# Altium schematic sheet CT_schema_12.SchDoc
size 281 x 153 mm
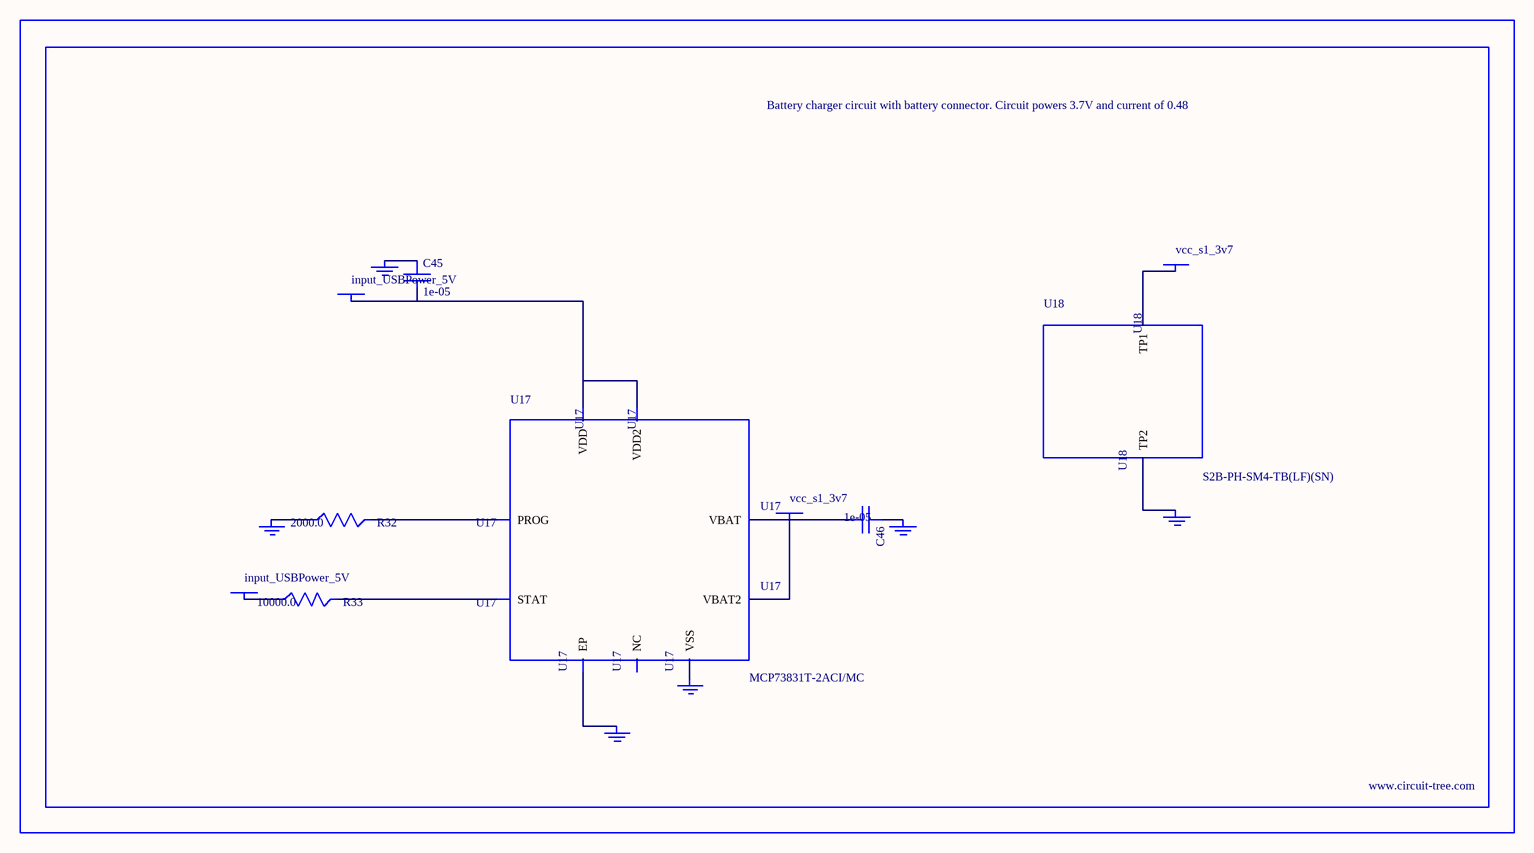
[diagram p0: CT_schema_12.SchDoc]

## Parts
BORDER11  (no value)
C45  1e-05  [C1206]
C46  1e-05  [C1206]
GND_INSTANCE_11_0  (no value)
GND_INSTANCE_11_1  (no value)
GND_INSTANCE_11_2  (no value)
GND_INSTANCE_11_3  (no value)
GND_INSTANCE_11_4  (no value)
GND_INSTANCE_11_5  (no value)
POWER_INSTANCE_11_0  input_USBPower_5V
POWER_INSTANCE_11_1  input_USBPower_5V
POWER_INSTANCE_11_2  vcc_s1_3v7
POWER_INSTANCE_11_3  vcc_s1_3v7
R32  2000.0  [R0603]
R33  10000.0  [R0603]
U17  MCP73831T-2ACI/MC  [DFN8_2X3MC]
U18  S2B-PH-SM4-TB(LF)(SN)  [JST-2-SMD]

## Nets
NetC45_1: C45.1 GND_INSTANCE_11_0.0(GND)
NetC45_2: C45.2 POWER_INSTANCE_11_0.0(PWR) U17.1(VDD) U17.2(VDD2)
NetC46_1: C46.1 GND_INSTANCE_11_1.0(GND)
NetC46_2: C46.2 POWER_INSTANCE_11_2.0(PWR) U17.3(VBAT) U17.4(VBAT2)
NetGND_INSTANCE_11_2_0: GND_INSTANCE_11_2.0(GND) R32.1
NetGND_INSTANCE_11_3_0: GND_INSTANCE_11_3.0(GND) U17.9(EP)
NetGND_INSTANCE_11_4_0: GND_INSTANCE_11_4.0(GND) U17.6(VSS)
NetGND_INSTANCE_11_5_0: GND_INSTANCE_11_5.0(GND) U18.2(TP2)
NetPOWER_INSTANCE_11_1_0: POWER_INSTANCE_11_1.0(PWR) R33.1
NetPOWER_INSTANCE_11_3_0: POWER_INSTANCE_11_3.0(PWR) U18.1(TP1)
NetR32_2: R32.2 U17.8(PROG)
NetR33_2: R33.2 U17.5(STAT)

Not connected (* = marked no-connect by the designer): U17 7(NC)

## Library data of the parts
BORDER11 = BORDER_PAGE11
C45 C46 = C1206C106K3RACTU
GND_INSTANCE_11_0-GND_INSTANCE_11_5 = GND
POWER_INSTANCE_11_0-POWER_INSTANCE_11_3 = PWR
R32 = RC0603JR-072KL
R33 = RC0603JR-0710KL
